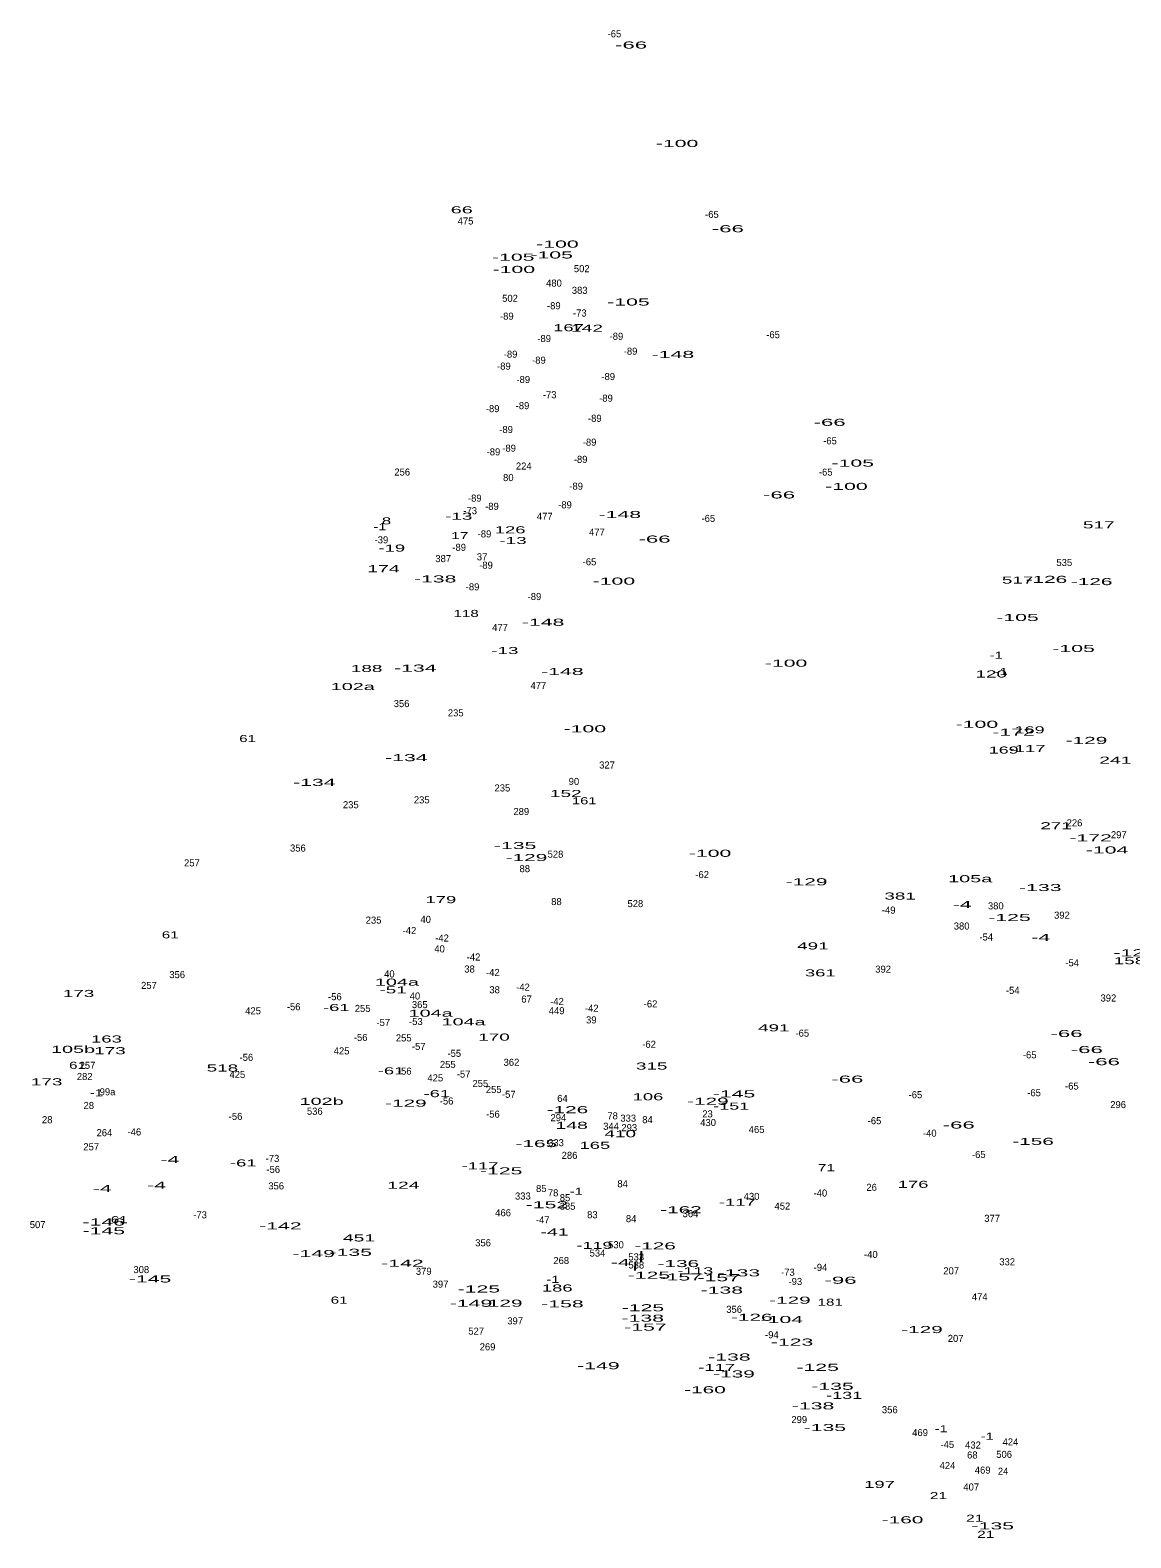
# Model space of a CAD drawing. Extents: x -662280 to -658689, y -991723 to -987042.
# Drawn here: x -662280 to -661656, y -990327 to -989473 of the extents above; entities that cross this region are included whole.
import ezdxf
from ezdxf.enums import TextEntityAlignment as Align

# ---------------------------------------------------------------- set-up
doc = ezdxf.new("R2010")
doc.units = 0
doc.header["$LTSCALE"] = 1.6
doc.layers.add('1', color=7, linetype='Continuous', lineweight=25)
doc.layers.add('24', color=7, linetype='Continuous')

msp = doc.modelspace()

# ---------------------------------------------------------------- linework, layer by layer
at = {"layer": '1'}
for p, q in [((-661933.68, -990171.03), (-661933.52, -990164.79)), ((-661937.08, -990170.97), (-661937.29, -990175.67))]:
    msp.add_line(p, q, dxfattribs=at)

# ---------------------------------------------------------------- texts
at = {"layer": '24'}
for s, p in [('-65', (-661948.85, -989476.65)), ('-65', (-661893.6, -989579.02)), ('475', (-662033.227, -989582.77)), ('502', (-661967.361, -989609.78)), ('480', (-661983.095, -989617.96)), ('383', (-661968.517, -989622.06)), ('502', (-662008.001, -989626.59)), ('-89', (-661983.19, -989630.79)), ('-89', (-662009.81, -989636.7)), ('-73', (-661968.471, -989634.92)), ('-65', (-661858.92, -989647.22)), ('-89', (-661988.68, -989649.39)), ('-89', (-661947.71, -989648.12)), ('-89', (-661939.68, -989656.57)), ('-89', (-662011.49, -989665.03)), ('-89', (-662007.69, -989658.26)), ('-89', (-661991.64, -989661.65)), ('-89', (-662000.51, -989672.64)), ('-89', (-661952.35, -989670.95)), ('-73', (-661985.561, -989681.24)), ('-89', (-662017.83, -989689.12)), ('-89', (-662000.93, -989687.43)), ('-89', (-661953.62, -989683.2)), ('-89', (-661959.96, -989694.62)), ('-89', (-662010.23, -989700.96)), ('-65', (-661826.66, -989707.34)), ('-89', (-662017.41, -989713.64)), ('-89', (-662008.54, -989711.53)), ('-89', (-661962.91, -989708.14)), ('224', (-662000.231, -989721.68)), ('-89', (-661967.98, -989717.87)), ('256', (-662069.113, -989725.07)), ('80', (-662008.971, -989728.21)), ('-89', (-661970.52, -989733.09)), ('-65', (-661829.08, -989725.1)), ('-89', (-662027.97, -989739.85)), ('-73', (-662030.571, -989747)), ('-89', (-662018.25, -989744.5)), ('477', (-661988.333, -989750.15)), ('-89', (-661976.85, -989743.65)), ('477', (-661958.753, -989759.08)), ('-65', (-661895.62, -989751.33)), ('-39', (-662080.9, -989763.49)), ('-89', (-662022.48, -989760.14)), ('387', (-662045.883, -989774.14)), ('-89', (-662036.84, -989767.75)), ('37', (-662023.843, -989773.1)), ('-65', (-661962.97, -989775.94)), ('-89', (-662021.63, -989777.89)), ('535', (-661693.877, -989776.34)), ('-89', (-662029.24, -989790.15)), ('-89', (-661994.17, -989795.65)), ('477', (-662013.653, -989813.13)), ('477', (-661991.943, -989846.1)), ('356', (-662069.483, -989856.33)), ('235', (-662038.787, -989861.59)), ('327', (-661953.033, -989891.14)), ('235', (-662012.337, -989904.13)), ('90', (-661971.787, -989900.44)), ('235', (-662058.047, -989910.9)), ('235', (-662098.257, -989913.65)), ('289', (-662001.623, -989917.49)), ('226', (-661688.083, -989923.92)), ('356', (-662128.233, -989938.21)), ('297', (-661662.998, -989930.66)), ('257', (-662188.303, -989946.63)), ('528', (-661982.247, -989941.69)), ('88', (-661999.637, -989949.88)), ('-62', (-661899.13, -989953.24)), ('88', (-661981.707, -989968.55)), ('528', (-661936.977, -989969.7)), ('380', (-661732.691, -989970.99)), ('235', (-662085.347, -989979.05)), ('40', (-662055.805, -989978.63)), ('-49', (-661793.415, -989973.37)), ('392', (-661695.213, -989976.25)), ('-42', (-662064.999, -989984.96)), ('-42', (-662046.529, -989989.22)), ('380', (-661752.051, -989982.41)), ('-54', (-661738.109, -989988.62)), ('40', (-662047.955, -989995.37)), ('38', (-662030.937, -990006.78)), ('-42', (-662028.679, -989999.98)), ('392', (-661796.563, -990006.85)), ('-54', (-661689.409, -990003.24)), ('356', (-662196.653, -990009.95)), ('40', (-662076.385, -990009.57)), ('-42', (-662017.719, -990008.72)), ('257', (-662212.643, -990016.05)), ('-56', (-662107.28, -990022.46)), ('40', (-662061.895, -990022.07)), ('38', (-662016.737, -990018.54)), ('-42', (-662000.669, -990017.04)), ('67', (-661998.638, -990023.79)), ('-54', (-661723.099, -990018.87)), ('392', (-661668.873, -990023.21)), ('425', (-662153.631, -990030.46)), ('-56', (-662130.64, -990028.15)), ('255', (-662091.537, -990029.11)), ('365', (-662059.173, -990026.95)), ('449', (-661981.591, -990030.39)), ('-42', (-661981.399, -990025.16)), ('-42', (-661961.709, -990029.02)), ('-62', (-661928.36, -990026.56)), ('-57', (-662079.861, -990037.09)), ('-53', (-662061.375, -990036.52)), ('39', (-661961.943, -990035.62)), ('-56', (-662092.66, -990045.56)), ('255', (-662068.257, -990045.83)), ('-62', (-661929.2, -990049.45)), ('-65', (-661842.36, -990043.12)), ('-56', (-662157.43, -990056.83)), ('425', (-662103.481, -990053.19)), ('-57', (-662059.741, -990050.65)), ('-55', (-662039.605, -990054.57)), ('-65', (-661713.49, -990055.44)), ('257', (-662247.493, -990061.36)), ('425', (-662162.551, -990066.58)), ('-56', (-662067.67, -990064.64)), ('255', (-662043.287, -990060.87)), ('-57', (-662034.321, -990066.33)), ('362', (-662007.203, -990059.65)), ('282', (-662249.077, -990067.68)), ('425', (-662050.371, -990068.49)), ('255', (-662024.867, -990071.65)), ('255', (-662017.257, -990075.04)), ('-65', (-661689.59, -990073.12)), ('99a', (-662236.123, -990076.38)), ('-56', (-662043.96, -990081.59)), ('-57', (-662008.701, -990077.78)), ('64', (-661978.287, -990080.12)), ('-65', (-661778.24, -990078.02)), ('-65', (-661711.02, -990076.9)), ('296', (-661663.378, -990083.63)), ('28', (-662270.307, -990092.19)), ('28', (-662246.757, -990084.11)), ('-56', (-662163.57, -990090.32)), ('536', (-662118.663, -990087.39)), ('-56', (-662017.7, -990089.01)), ('294', (-661980.617, -990091.03)), ('78', (-661949.873, -990090.02)), ('333', (-661941.017, -990091.32)), ('84', (-661930.111, -990092.16)), ('23', (-661896.077, -990088.91)), ('264', (-662237.887, -990099.55)), ('-46', (-662220.925, -990099.14)), ('344', (-661950.746, -990095.91)), ('293', (-661940.423, -990096.7)), ('430', (-661895.755, -990093.81)), ('465', (-661868.257, -990097.73)), ('-65', (-661801.43, -990092.75)), ('-40', (-661770.123, -990099.85)), ('257', (-662245.373, -990107.54)), ('333', (-661981.957, -990105.22)), ('-73', (-662142.641, -990114.13)), ('286', (-661974.273, -990112.4)), ('-65', (-661742.35, -990111.92)), ('-56', (-662142.22, -990120.37)), ('356', (-662140.553, -990129.71)), ('85', (-661990.287, -990131.2)), ('78', (-661983.593, -990133.65)), ('84', (-661944.201, -990128.5)), ('-40', (-661832.103, -990133.76)), ('26', (-661803.053, -990130.53)), ('333', (-662000.727, -990135.46)), ('385', (-661975.387, -990141.24)), ('85', (-661976.827, -990136.4)), ('430', (-661871.105, -990135.67)), ('452', (-661853.641, -990141.15)), ('507', (-662275.727, -990151.67)), ('-73', (-662183.671, -990146.12)), ('466', (-662011.943, -990144.92)), ('-47', (-661989.495, -990148.98)), ('83', (-661961.347, -990146.07)), ('84', (-661939.371, -990148.29)), ('364', (-661905.717, -990145.45)), ('377', (-661734.769, -990148.11)), ('356', (-662023.273, -990161.96)), ('534', (-661958.451, -990167.78)), ('530', (-661947.961, -990163.06)), ('-40', (-661803.493, -990168.56)), ('308', (-662216.991, -990177.16)), ('268', (-661978.993, -990172.03)), ('533', (-661936.497, -990169.98)), ('538', (-661936.437, -990174.54)), ('-94', (-661832.045, -990175.89)), ('207', (-661757.997, -990177.86)), ('332', (-661726.237, -990172.73)), ('379', (-662056.908, -990178.11)), ('397', (-662047.398, -990185.42)), ('-73', (-661850.521, -990178.64)), ('-93', (-661846.31, -990183.89)), ('474', (-661741.791, -990192.57)), ('356', (-661880.993, -990199.67)), ('527', (-662027.203, -990212.07)), ('397', (-662005.108, -990206.24)), ('-94', (-661859.595, -990214.08)), ('207', (-661755.457, -990216.16)), ('269', (-662020.738, -990220.92)), ('299', (-661844.098, -990262.18)), ('356', (-661792.783, -990256.58)), ('469', (-661775.623, -990269.55)), ('-45', (-661760.179, -990276.3)), ('432', (-661745.631, -990276.6)), ('424', (-661724.396, -990274.84)), ('424', (-661760.086, -990288.22)), ('68', (-661745.993, -990282.25)), ('506', (-661727.977, -990281.88)), ('469', (-661740.133, -990290.8)), ('24', (-661728.561, -990291.46)), ('407', (-661746.611, -990300.39))]:
    msp.add_text(s, height=4, dxfattribs=at).set_placement(p, align=Align.CENTER)
for s, width, p in [('-66', 2.35, (-661939.393, -989483.02)), ('-100', 2.25, (-661913.333, -989538.8)), ('66', 2.1, (-662035.361, -989576.43)), ('-66', 2.35, (-661884.543, -989587.13)), ('-100', 2.25, (-661981.143, -989595.85)), ('-105', 2.25, (-662006.177, -989603.28)), ('-105', 2.25, (-661984.417, -989602.01)), ('-100', 2.25, (-662005.853, -989610.22)), ('-105', 2.25, (-661940.897, -989628.68)), ('167', 1.95, (-661974.867, -989643.24)), ('142', 2.05, (-661964.423, -989643.55)), ('-148', 2.25, (-661915.676, -989658.41)), ('-66', 2.35, (-661826.873, -989696.89)), ('-105', 2.25, (-661813.747, -989719.99)), ('-100', 2.25, (-661817.333, -989733.21)), ('-66', 2.35, (-661855.513, -989738.04)), ('-13', 2, (-662037.091, -989750.11)), ('-148', 2.25, (-661945.746, -989749.12)), ('-1', 1.55, (-662081.721, -989756.04)), ('8', 1.8, (-662078.021, -989752.75)), ('126', 1.95, (-662007.943, -989757.8)), ('517', 2, (-661674.353, -989755.02)), ('17', 1.65, (-662036.473, -989761.11)), ('-13', 2, (-662006.321, -989763.87)), ('-66', 2.35, (-661926.083, -989763.06)), ('-19', 1.95, (-662075.005, -989768.17)), ('174', 2.05, (-662079.728, -989779.86)), ('-138', 2.25, (-662050.441, -989785.66)), ('-100', 2.25, (-661949.133, -989786.89)), ('517', 2, (-661720.313, -989786.3)), ('-126', 2.2, (-661704.025, -989785.91)), ('-126', 2.2, (-661678.365, -989787.17)), ('118', 1.6, (-662032.874, -989805.21)), ('-148', 2.25, (-661989.256, -989810.23)), ('-105', 2.25, (-661720.387, -989807.5)), ('-13', 2, (-662010.981, -989826.25)), ('-105', 2.25, (-661688.597, -989825.1)), ('-100', 2.25, (-661851.553, -989833.39)), ('-1', 1.55, (-661732.441, -989828.9)), ('188', 2, (-662089.277, -989836.42)), ('-134', 2.25, (-662061.696, -989836.2)), ('-148', 2.25, (-661978.346, -989838.12)), ('120', 2, (-661735.284, -989839.54)), ('-1', 1.55, (-661729.601, -989838.17)), ('102a', 2.1, (-662097.129, -989846.66)), ('-100', 2.25, (-661743.403, -989868.05)), ('61', 1.6, (-662156.733, -989876.15)), ('-100', 2.25, (-661965.613, -989870.59)), ('-172', 2.25, (-661722.665, -989872.49)), ('169', 1.9, (-661713.517, -989871.2)), ('-129', 2.2, (-661681.315, -989877.2)), ('-134', 2.25, (-662066.766, -989886.96)), ('169', 1.9, (-661728.217, -989882.65)), ('-117', 1.95, (-661714.971, -989881.79)), ('241', 2.05, (-661664.923, -989888.39)), ('-134', 2.25, (-662118.916, -989900.97)), ('152', 2, (-661976.397, -989907.27)), ('161', 1.55, (-661965.939, -989911.39)), ('271', 2, (-661698.523, -989925.56)), ('-135', 2.25, (-662005.121, -989936.78)), ('-172', 2.25, (-661678.945, -989932.41)), ('-129', 2.2, (-661998.695, -989943.58)), ('-100', 2.25, (-661894.643, -989941.18)), ('-104', 2.25, (-661669.652, -989939.3)), ('105a', 2.1, (-661747.209, -989955.58)), ('-129', 2.2, (-661839.915, -989957.33)), ('-133', 2.25, (-661707.491, -989960.6)), ('179', 1.95, (-662047.197, -989967.44)), ('381', 2, (-661786.917, -989965.41)), ('-4', 2.25, (-661751.76, -989970.26)), ('-125', 2.25, (-661724.931, -989977.56)), ('61', 1.6, (-662200.603, -989987.4)), ('-4', 2.25, (-661707.2, -989988.85)), ('491', 2, (-661836.388, -989993.7)), ('-125', 2.25, (-661653.981, -989997.56)), ('158', 2, (-661656.927, -990002.07)), ('104a', 2.1, (-662072.105, -990014.2)), ('361', 1.95, (-661832.163, -990008.97)), ('173', 2, (-662252.553, -990020.62)), ('-51', 2, (-662074.261, -990018.56)), ('-61', 1.95, (-662106.455, -990028.59)), ('104a', 2.1, (-662053.005, -990031.82)), ('104a', 2.1, (-662034.335, -990036.7)), ('491', 2, (-661858.508, -990040.09)), ('163', 1.95, (-662236.723, -990046.44)), ('170', 2, (-662017.059, -990045.36)), ('-66', 2.35, (-661692.603, -990043.35)), ('105b', 2.1, (-662255.669, -990052.3)), ('173', 2, (-662234.733, -990053.08)), ('-66', 2.35, (-661681.103, -990052.43)), ('61', 1.6, (-662253.133, -990061.37)), ('518', 2, (-662171.007, -990062.89)), ('-61', 1.95, (-662075.435, -990064.49)), ('315', 2, (-661927.717, -990061.77)), ('-66', 2.35, (-661671.423, -990059.29)), ('173', 2, (-662270.593, -990070.69)), ('-66', 2.35, (-661816.813, -990069.18)), ('-1', 1.55, (-662242.421, -990076.92)), ('102b', 2.1, (-662114.789, -990081.77)), ('-129', 2.2, (-662067.055, -990082.82)), ('-61', 1.95, (-662049.485, -990077.42)), ('106', 1.95, (-661929.809, -990079.18)), ('-129', 2.2, (-661895.865, -990081.76)), ('-145', 2.25, (-661881.046, -990077.58)), ('-145', 2.25, (-661881.046, -990077.58)), ('-126', 2.2, (-661975.465, -990086.51)), ('-151', 1.9, (-661882.637, -990084.48)), ('148', 2.05, (-661973.043, -990095.4)), ('410', 2, (-661945.529, -990100.14)), ('-66', 2.35, (-661753.693, -990095.21)), ('-165', 2.2, (-661993.095, -990105.74)), ('165', 1.95, (-661959.923, -990106.71)), ('-156', 2.2, (-661711.555, -990104.48)), ('-4', 2.25, (-662200.8, -990114.8)), ('-61', 1.95, (-662159.185, -990116.7)), ('-117', 1.95, (-662025.011, -990118.35)), ('-125', 2.25, (-662013.021, -990121.2)), ('71', 1.65, (-661828.673, -990119.38)), ('-4', 2.25, (-662239.13, -990131.2)), ('-4', 2.25, (-662208.37, -990129.36)), ('124', 2.05, (-662068.473, -990129.33)), ('-1', 1.55, (-661970.431, -990132.78)), ('176', 1.95, (-661779.567, -990128.84)), ('-152', 2.25, (-661987.081, -990140.39)), ('-162', 2.2, (-661911.105, -990143.23)), ('-117', 1.95, (-661879.191, -990138.99)), ('-146', 2.25, (-662238.271, -990150.18)), ('61', 1.6, (-662229.503, -990148.87)), ('-145', 2.25, (-662238.226, -990155.15)), ('-142', 2.25, (-662138.176, -990152.4)), ('451', 2.05, (-662093.603, -990159.22)), ('-41', 2.05, (-661982.766, -990155.85)), ('-149', 2.25, (-662119.281, -990168.07)), ('-135', 2.25, (-662098.281, -990167.35)), ('-119', 1.9, (-661960.141, -990163.43)), ('-126', 2.2, (-661925.815, -990163.73)), ('-142', 2.25, (-662068.976, -990173.58)), ('-4', 2.25, (-661945.5, -990173.08)), ('-136', 2.2, (-661912.615, -990173.74)), ('-113', 1.9, (-661902.987, -990177.84)), ('-145', 2.25, (-662212.016, -990182.46)), ('-1', 1.55, (-661983.741, -990182.68)), ('-125', 2.25, (-661929.281, -990180.36)), ('-157', 2.25, (-661911.235, -990181.34)), ('-157', 2.25, (-661889.725, -990181.75)), ('-133', 2.25, (-661878.291, -990179)), ('-96', 2.35, (-661820.693, -990183.2)), ('61', 1.6, (-662104.903, -990194.44)), ('-125', 2.25, (-662025.671, -990188.15)), ('186', 1.95, (-661981.263, -990187.6)), ('-138', 2.25, (-661887.961, -990188.78)), ('-129', 2.2, (-661849.405, -990194.52)), ('-149', 2.25, (-662030.131, -990196.26)), ('-129', 2.2, (-662012.705, -990196.19)), ('-158', 2.25, (-661978.291, -990196.58)), ('-125', 2.25, (-661932.661, -990198.78)), ('181', 1.6, (-661826.554, -990195.6)), ('-138', 2.25, (-661932.791, -990204.68)), ('-157', 2.25, (-661931.275, -990209.77)), ('-126', 2.2, (-661870.995, -990204.2)), ('-104', 2.25, (-661853.972, -990205.46)), ('-129', 2.2, (-661774.535, -990211.15)), ('-123', 2.25, (-661848.141, -990218.25)), ('-138', 2.25, (-661883.671, -990226.72)), ('-149', 2.25, (-661957.931, -990231.65)), ('-117', 1.95, (-661890.881, -990232.6)), ('-139', 2.2, (-661881.065, -990236.31)), ('-125', 2.25, (-661833.641, -990232.56)), ('-160', 2.2, (-661897.521, -990245.26)), ('-135', 2.25, (-661825.251, -990243.3)), ('-138', 2.25, (-661836.281, -990254.39)), ('-131', 1.9, (-661818.587, -990248.43)), ('-135', 2.25, (-661829.581, -990266.69)), ('-1', 1.55, (-661763.681, -990267.36)), ('-1', 1.55, (-661737.531, -990271.58)), ('-1', 1.55, (-661737.531, -990271.58)), ('197', 1.95, (-661798.587, -990298.92)), ('21', 1.65, (-661765.197, -990305.29)), ('-160', 2.2, (-661785.531, -990318.97)), ('21', 1.65, (-661744.647, -990318.11)), ('-135', 2.25, (-661734.421, -990322.43)), ('21', 1.65, (-661738.387, -990327.22))]:
    msp.add_text(s, height=4, dxfattribs=dict(at, width=width)).set_placement(p, align=Align.CENTER)

doc.saveas('drawing.dxf')
